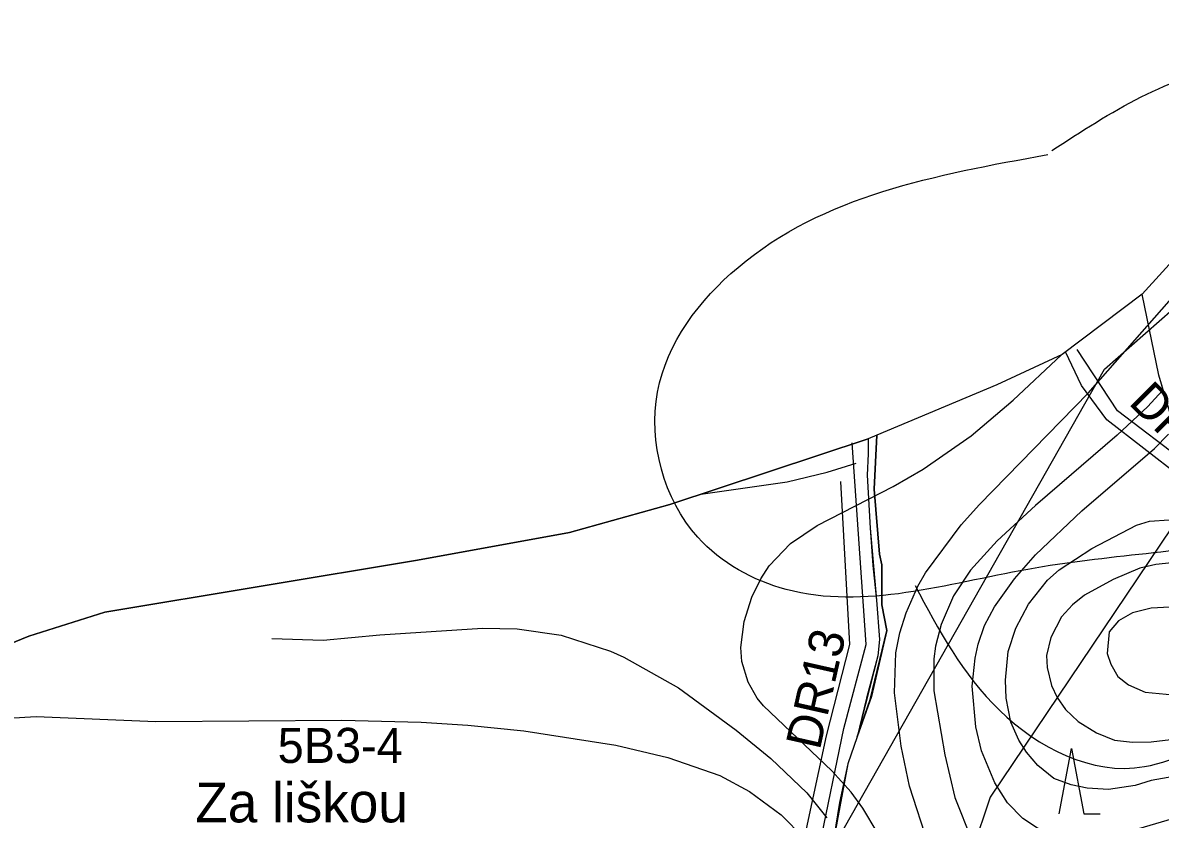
# Model space of a CAD drawing. Extents: x -684583 to -680383, y -1157874 to -1154904.
# Drawn here: x -684293.9 to -683807, y -1157337.4 to -1156996.7 of the extents above; entities that cross this region are included whole.
import ezdxf

# ---------------------------------------------------------------- set-up
doc = ezdxf.new("R2010")
doc.units = 0
for name, color, linetype in [('01_MÍSTNÍ_NÁZVY', 7, 'Continuous'), ('01_OBVOD PÚ', 7, 'Continuous'), ('01_SPRÁV_HRANICE', 7, 'Continuous'), ('01_VRSTEVNICE', 7, 'Continuous'), ('02_KULTURY STAV', 7, 'Continuous'), ('03_PC_OBJEKTY_NÁVRH', 7, 'Continuous'), ('03_PC_STAV', 7, 'Continuous'), ('06_BIOGEOGRAFIE', 7, 'Continuous'), ('06_ÚSES_BK', 7, 'Continuous')]:
    doc.layers.add(name, color=color, linetype=linetype)

msp = doc.modelspace()

# ---------------------------------------------------------------- linework, layer by layer
at = {"layer": '01_OBVOD PÚ'}
msp.add_lwpolyline([(-683790.05, -1157085.64), (-683814.83, -1157112.74), (-683848.99, -1157138.51), (-683877.01, -1157151.57), (-683928.38, -1157173.08), (-683932.06, -1157174.67), (-684016.98, -1157202.73), (-684059.94, -1157214.73), (-684124.97, -1157226.52), (-684258.76, -1157248.75), (-684291.25, -1157258.99), (-684320, -1157270.76)], dxfattribs=at)
at = {"layer": '01_SPRÁV_HRANICE'}
msp.add_lwpolyline([(-683790.05, -1157085.64), (-683814.83, -1157112.74), (-683848.99, -1157138.51), (-683877.01, -1157151.57), (-683928.38, -1157173.08), (-683932.06, -1157174.67), (-684016.98, -1157202.73), (-684059.94, -1157214.73), (-684124.97, -1157226.52), (-684258.76, -1157248.75), (-684291.25, -1157258.99), (-684320, -1157270.76)], dxfattribs=at)
at = {"layer": '01_VRSTEVNICE'}
for points in [[(-683906.21, -1157348.31), (-683914.34, -1157323.21), (-683917.91, -1157306.09), (-683920.76, -1157283.27), (-683920.19, -1157266.15), (-683918.48, -1157257.59), (-683915.77, -1157249.03), (-683910.78, -1157237.62), (-683907.49, -1157231.92), (-683892.23, -1157211.37), (-683884.39, -1157202.67), (-683837.88, -1157155.17), (-683797.94, -1157109.81)], [(-683928.18, -1157342.89), (-683934.31, -1157332.62), (-683939.3, -1157325.78), (-683947.58, -1157316.65), (-683976.82, -1157288.83), (-683979.53, -1157285.55), (-683983.38, -1157278.7), (-683986.09, -1157269.86), (-683986.52, -1157263.87), (-683985.09, -1157252.74), (-683981.81, -1157242.33), (-683977.96, -1157234.48), (-683974.4, -1157228.92), (-683965.27, -1157219.36), (-683953.85, -1157211.66), (-683921.33, -1157194.97), (-683908.49, -1157187.55), (-683887.95, -1157173.29), (-683869.98, -1157158.03), (-683849.31, -1157138.66)], [(-683806.22, -1157154.17), (-683812.35, -1157160.74), (-683825.47, -1157173), (-683860.42, -1157203.1), (-683876.83, -1157218.22), (-683888.24, -1157230.77), (-683895.51, -1157241.76), (-683900.79, -1157254.03), (-683903.22, -1157263.3), (-683903.93, -1157268.72), (-683903.93, -1157282.41), (-683899.22, -1157309.8), (-683894.94, -1157328.06), (-683887.67, -1157346.32), (-683882.67, -1157355.45), (-683876.26, -1157364.15), (-683871.69, -1157368.43), (-683866.56, -1157372.13), (-683861.14, -1157374.27), (-683852.58, -1157375.41), (-683843.45, -1157374.56), (-683804.65, -1157362.01)], [(-683801.8, -1157337.19), (-683821.2, -1157342.89), (-683822.48, -1157342.75), (-683822.76, -1157343.32), (-683835.17, -1157344.75), (-683844.59, -1157344.89), (-683849.72, -1157344.18), (-683859.57, -1157341.18), (-683865.84, -1157337.04), (-683872.4, -1157330.34), (-683877.83, -1157321.78), (-683883.53, -1157308.09), (-683885.95, -1157297.82), (-683887.53, -1157280.41), (-683886.24, -1157268.43), (-683884.96, -1157262.44), (-683882.25, -1157254.45), (-683877.97, -1157246.46), (-683869.41, -1157234.48), (-683860.42, -1157224.21), (-683840.59, -1157205.38), (-683809.5, -1157178.71), (-683803.51, -1157172.58)], [(-684003.7, -1157198.34), (-683966.69, -1157192.97), (-683949.58, -1157188.84), (-683937.17, -1157184.98)], [(-683797.23, -1157318.36), (-683810.92, -1157320.78), (-683817.77, -1157322.92), (-683829.18, -1157324.63), (-683838.31, -1157324.06), (-683845.16, -1157322.64), (-683852.58, -1157319.93), (-683859.42, -1157314.36), (-683864.27, -1157308.66), (-683867.55, -1157303.52), (-683870.98, -1157295.82), (-683872.97, -1157285.55), (-683873.26, -1157277.85), (-683872.12, -1157265.58), (-683868.84, -1157255.59), (-683863.42, -1157245.32), (-683855.29, -1157235.05), (-683850.29, -1157230.63), (-683836.32, -1157221.5), (-683817.2, -1157211.52), (-683811.64, -1157209.81), (-683803.22, -1157209.23)], [(-683802.08, -1157227.64), (-683808.93, -1157228.35), (-683815.78, -1157229.92), (-683827.19, -1157234.77), (-683839.45, -1157241.47), (-683844.59, -1157245.61), (-683849.3, -1157250.74), (-683853.86, -1157259.59), (-683855.71, -1157267.29), (-683855.43, -1157272.43), (-683853.58, -1157280.13), (-683851.15, -1157285.26), (-683847.58, -1157290.4), (-683842.16, -1157295.53), (-683834.32, -1157300.38), (-683826.62, -1157303.52), (-683818.91, -1157304.38), (-683810.92, -1157304.24), (-683788.1, -1157301.53)], [(-684187.31, -1157260.04), (-684165.25, -1157260.73), (-684141, -1157258.45), (-684097.07, -1157255.59), (-684082.23, -1157255.88), (-684063.41, -1157258.59), (-684042.29, -1157265.44), (-684036.59, -1157268), (-684013.19, -1157281.13), (-683988.52, -1157299.24), (-683973.68, -1157311.37), (-683958.28, -1157326.06), (-683949.72, -1157336.76)], [(-684300.19, -1157294.11), (-684288.21, -1157293.39), (-684236.86, -1157295.53), (-684157.26, -1157294.96), (-684123.32, -1157295.82), (-684103.34, -1157297.1), (-684079.38, -1157299.53), (-684040.01, -1157305.66), (-684017.76, -1157310.94), (-683995.51, -1157318.64), (-683982.81, -1157325.49), (-683969.26, -1157335.47), (-683959.42, -1157345.46)]]:
    msp.add_lwpolyline(points, dxfattribs=at)
msp.add_lwpolyline([(-683798.94, -1157247.18), (-683802.94, -1157246.61), (-683810.92, -1157247.03), (-683818.91, -1157249.03), (-683824.9, -1157252.46), (-683828.9, -1157257.16), (-683829.75, -1157266.43), (-683828.18, -1157271), (-683825.19, -1157276.28), (-683820.62, -1157279.84), (-683813.49, -1157282.98), (-683801.51, -1157284.12), (-683768.13, -1157285.12), (-683760.43, -1157284.27), (-683755.29, -1157282.84), (-683748.16, -1157278.13), (-683748.45, -1157271.57), (-683750.3, -1157267.72), (-683755.58, -1157263.15), (-683766.13, -1157257.31)], close=True, dxfattribs=at)
at = {"layer": '02_KULTURY STAV'}
for points in [[(-683794.67, -1157191.18), (-683807.61, -1157147.35), (-683814.83, -1157112.74), (-683790.05, -1157085.64)], [(-683792.57, -1157198.29), (-683807.61, -1157147.35), (-683814.83, -1157112.74), (-683848.99, -1157138.51), (-683877.01, -1157151.57), (-683928.38, -1157173.08), (-683929.51, -1157196.21), (-683927.23, -1157224.03), (-683926.2, -1157228.59), (-683926.14, -1157245.68), (-683924.11, -1157256.57), (-683930.66, -1157284.82), (-683936.81, -1157302.12), (-683940.7, -1157313.6), (-683944.31, -1157330.16), (-683947.59, -1157350.45)], [(-684320, -1157270.76), (-684291.25, -1157258.99), (-684258.76, -1157248.75), (-684124.97, -1157226.52), (-684059.94, -1157214.73), (-684016.98, -1157202.73), (-683932.06, -1157174.67), (-683932.06, -1157181.01), (-683932.52, -1157190.13), (-683931.26, -1157212.89), (-683928.46, -1157243.64), (-683927.23, -1157260.45), (-683927.9, -1157267.42), (-683936.81, -1157302.12), (-683940.7, -1157313.6), (-683947.59, -1157350.45)], [(-683850.26, -1157335.06), (-683845.01, -1157307.06), (-683839.76, -1157335.06), (-683832.76, -1157335.06)]]:
    msp.add_lwpolyline(points, dxfattribs=at)
msp.add_lwpolyline([(-683928.38, -1157173.08), (-683932.06, -1157174.67), (-683932.06, -1157181.01), (-683932.52, -1157190.13), (-683931.26, -1157212.89), (-683929.98, -1157228.82), (-683928.46, -1157243.64), (-683927.23, -1157260.45), (-683927.9, -1157267.42), (-683932.8, -1157285.57), (-683936.81, -1157302.12), (-683931.13, -1157286.14), (-683924.11, -1157256.57), (-683926.14, -1157245.68), (-683926.2, -1157228.59), (-683927.23, -1157224.03), (-683929.51, -1157196.21)], close=True, dxfattribs=at)
at = {"layer": '03_PC_OBJEKTY_NÁVRH'}
for points in [[(-683756.99, -1157215.27), (-683770.13, -1157208.02), (-683796.14, -1157184.95), (-683825.37, -1157162.68), (-683842.54, -1157136.38)], [(-683943.86, -1157192.93), (-683940.03, -1157262.66), (-683949.99, -1157301.75), (-683959.42, -1157345.46), (-683977.31, -1157386.04), (-683999.01, -1157435.6), (-684010.76, -1157492.05), (-684004.63, -1157515.56)]]:
    msp.add_lwpolyline(points, dxfattribs=at)
at = {"layer": '03_PC_STAV'}
for points in [[(-683664.78, -1157266.53), (-683697.31, -1157253.23), (-683719.91, -1157236.08), (-683772.93, -1157212.56), (-683798.25, -1157190.98), (-683829.93, -1157166.44), (-683840.72, -1157151.79), (-683847.53, -1157137.36)], [(-683996.97, -1157522.67), (-684004.23, -1157490.53), (-683992.87, -1157435.78), (-683971.07, -1157384.89), (-683952.89, -1157348.98), (-683942.46, -1157298.55), (-683932.92, -1157262.66), (-683938.83, -1157176.33)]]:
    msp.add_lwpolyline(points, dxfattribs=at)
at = {"layer": '06_BIOGEOGRAFIE'}
for points in [[(-683662.04, -1156787.77), (-683658.6, -1156877.34), (-683631.05, -1156927.29), (-683541.5, -1156975.52), (-683489.85, -1157028.92), (-683414.08, -1157027.2), (-683362.42, -1157025.48), (-683360.7, -1157063.37), (-683464.02, -1157132.27), (-683493.29, -1157163.28), (-683474.35, -1157189.11), (-683407.19, -1157171.89), (-683317.65, -1157115.05), (-683269.44, -1157104.71), (-683207.44, -1157173.61), (-683186.78, -1157259.74), (-683105.85, -1157416.48), (-683069.69, -1157530.17), (-683073.13, -1157580.12), (-683097.24, -1157628.35), (-683264.27, -1157657.63), (-683431.3, -1157647.3), (-683531.17, -1157605.96), (-683636.21, -1157542.23), (-683651.71, -1157521.56), (-683682.7, -1157519.83), (-683708.53, -1157528.45), (-683818.74, -1157547.39), (-683870.4, -1157518.11), (-683980.6, -1157521.56), (-684052.92, -1157490.55), (-684171.74, -1157400.98), (-684213.07, -1157375.14), (-684250.95, -1157388.92), (-684249.23, -1157437.15), (-684237.17, -1157466.44), (-684170.02, -1157518.11), (-684097.7, -1157562.9), (-684011.6, -1157605.96), (-683953.05, -1157602.51), (-683891.06, -1157626.63), (-683835.96, -1157619.74), (-683789.47, -1157599.07), (-683713.7, -1157578.4), (-683625.88, -1157592.18), (-683551.84, -1157667.97), (-683445.07, -1157736.87), (-683346.92, -1157771.32), (-683179.89, -1157767.87), (-683081.74, -1157773.04), (-683016.71, -1157810.65), (-682999.16, -1157844)], [(-683853.43, -1157051.33), (-683774.22, -1157015.15), (-683705.34, -1157032.38), (-683667.46, -1157113.34), (-683696.73, -1157189.13), (-683762.17, -1157216.69), (-683863.76, -1157230.47), (-683967.08, -1157239.08), (-684004.96, -1157216.69), (-684022.18, -1157154.68), (-683987.74, -1157101.28), (-683855.15, -1157053.05)], [(-684058.34, -1157481.95), (-683939.53, -1157445.78), (-683724.28, -1157326.93), (-683638.18, -1157271.81), (-683500.43, -1157218.41), (-683460.82, -1157194.29)], [(-683911.98, -1157237.36), (-683875.81, -1157290.75), (-683813.82, -1157314.87), (-683736.34, -1157289.03), (-683710.51, -1157313.15)]]:
    msp.add_spline(points, degree=3, dxfattribs=at)
at = {"layer": '06_ÚSES_BK'}
for points in [[(-683996.04, -1157516.81), (-683998.85, -1157488.48), (-683996.64, -1157467.19), (-683991.24, -1157448.33), (-683989.06, -1157434.53), (-683985.68, -1157428.23), (-683976.94, -1157407.83), (-683968.87, -1157394.43), (-683960.84, -1157381.32), (-683955.69, -1157373.26), (-683947.59, -1157350.45), (-683830.91, -1157144.86), (-683778.26, -1157098.63)], [(-683792.57, -1157198.29), (-683879.8, -1157327.93), (-683925.26, -1157463.04), (-683942.47, -1157474.27), (-683972.51, -1157496.68), (-683982.82, -1157505.23), (-683996.04, -1157516.81)]]:
    msp.add_lwpolyline(points, dxfattribs=at)

# ---------------------------------------------------------------- texts
at = {"layer": '01_MÍSTNÍ_NÁZVY'}
msp.add_text('Za liškou', height=17, dxfattribs=at).set_placement((-684220.01, -1157338.7))
at = {"layer": '03_PC_OBJEKTY_NÁVRH'}
for s, rotation, p in [('DR19', 315.057, (-683820.97, -1157159.53)), ('DR13', 77.2863, (-683952.78, -1157308.15))]:
    msp.add_text(s, height=15, rotation=rotation, dxfattribs=at).set_placement(p)
at = {"layer": '06_BIOGEOGRAFIE'}
msp.add_text('5B3-4', height=15, dxfattribs=at).set_placement((-684184.78, -1157313.29))

doc.saveas('drawing.dxf')
